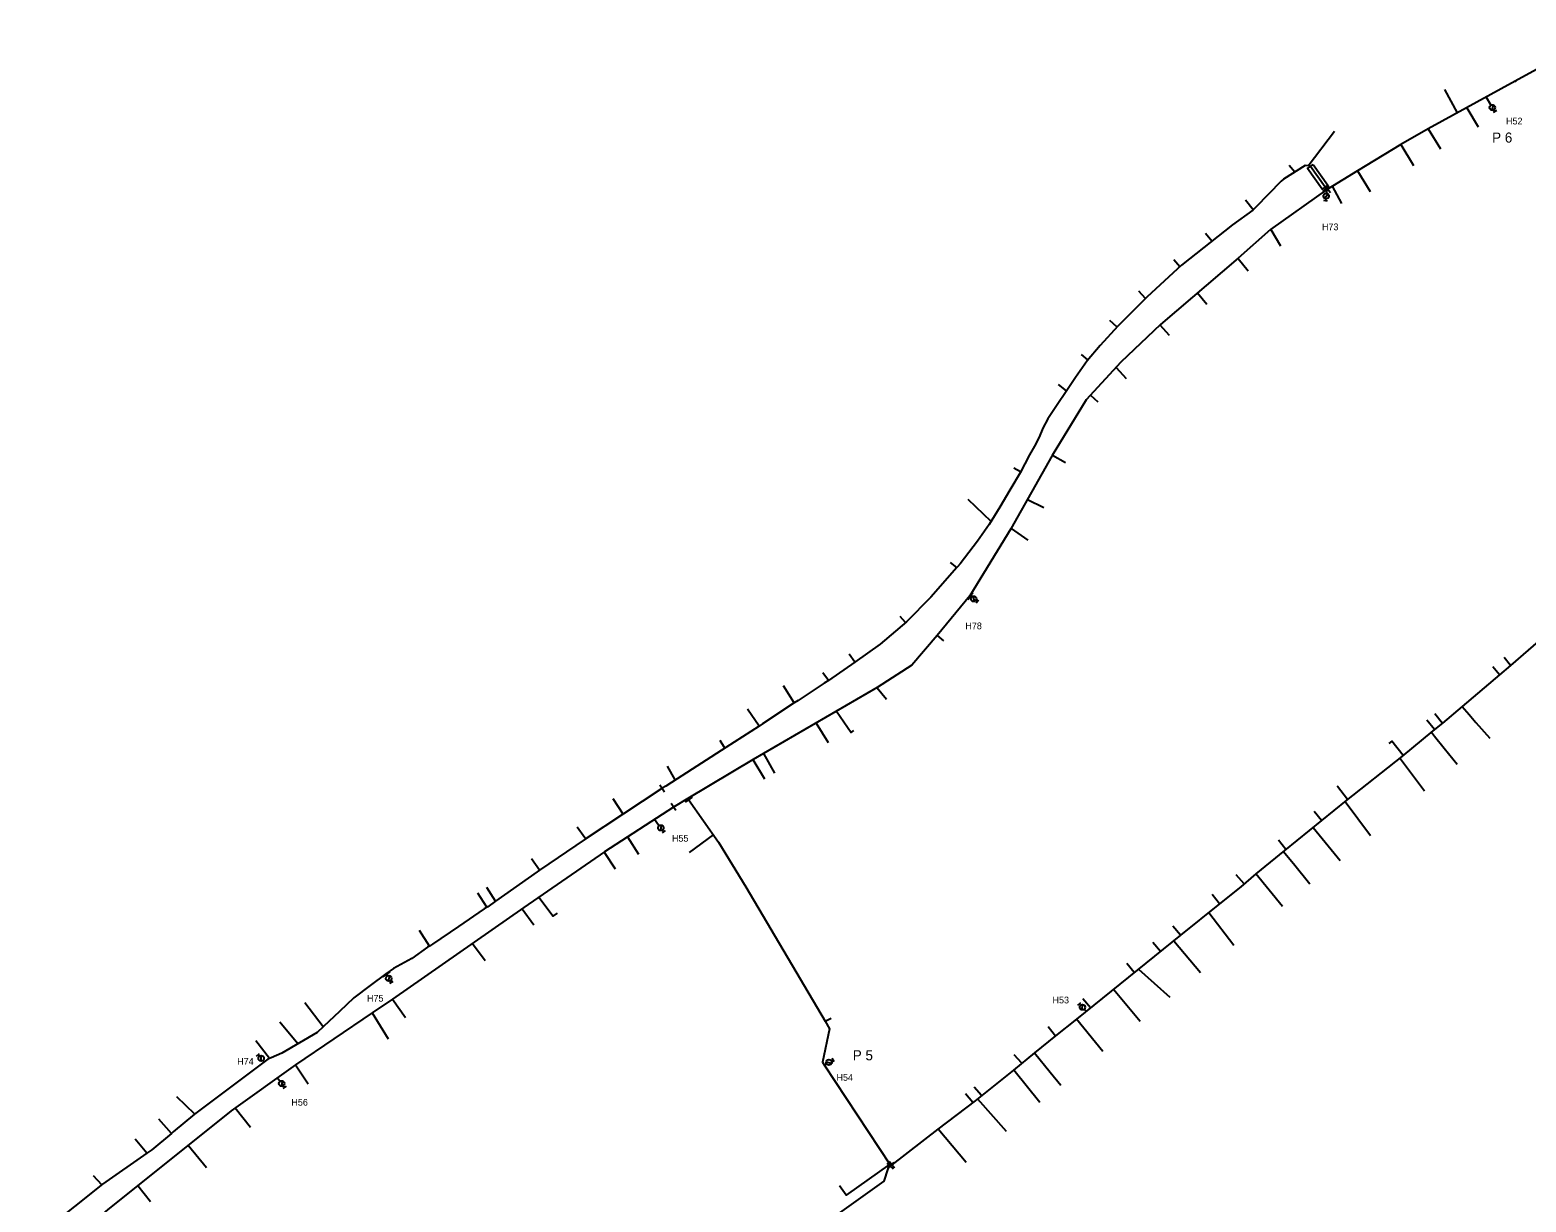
# Model space of a CAD drawing. Extents: x -548873 to -538270, y -1201997 to -1192514.
# Drawn here: x -548075.5 to -547630.3, y -1196272.7 to -1195923.8 of the extents above; entities that cross this region are included whole.
import ezdxf

# ---------------------------------------------------------------- set-up
doc = ezdxf.new("R2010")
doc.units = 0
for name, color, linetype in [('KN_HRAN_STÁTNÍ', 7, 'Continuous'), ('KN_PARC_Č', 7, 'Continuous'), ('KN_VKP_HRAN_SPORNÁ', 7, 'Continuous'), ('PK_PARC_Čv', 7, 'Continuous'), ('Vrstva 29', 7, 'Continuous'), ('Vrstva 37', 7, 'Continuous')]:
    doc.layers.add(name, color=color, linetype=linetype)

# ---------------------------------------------------------------- blocks, each defined once
blk = doc.blocks.new('160')
at = {"layer": 'KN_HRAN_STÁTNÍ'}
blk.add_circle((0, 0), 0.0458, dxfattribs=at)
blk = doc.blocks.new('147')
at = {"layer": 'KN_HRAN_STÁTNÍ'}
blk.add_line((0, 1.27), (0, -1.27), dxfattribs=at)
blk = doc.blocks.new('133')
at = {"layer": 'KN_HRAN_STÁTNÍ'}
for p, q in [((0.28, 0), (0, 0)), ((0.54, 0.58), (1.7, -0.58)), ((1.94, 0), (2.52, 0)), ((2.52, 0.58), (2.52, -0.58))]:
    blk.add_line(p, q, dxfattribs=at)
blk.add_circle((1.11, 0), 0.825, dxfattribs=at)
blk = doc.blocks.new('150')
at = {"layer": 'KN_HRAN_STÁTNÍ'}
blk.add_line((0, 1.27), (0, -1.27), dxfattribs=at)

msp = doc.modelspace()

# ---------------------------------------------------------------- linework, layer by layer
at = {"layer": 'KN_PARC_Č'}
for points in [[(-547650.72, -1195948.422), (-547654.526, -1195941.455)], [(-547647.993, -1195946.932), (-547644.598, -1195952.643)], [(-547659.454, -1195953.193), (-547655.801, -1195959.185)], [(-547695.179, -1195964.212), (-547687.375, -1195953.867)], [(-547667.61, -1195957.858), (-547663.867, -1195964.123)], [(-547699.188, -1195966.12), (-547700.829, -1195964.078)], [(-547680.509, -1195965.705), (-547676.747, -1195971.908)], [(-547688.06, -1195970.3), (-547685.271, -1195975.46)], [(-547676.877, -1195971.694), (-547676.665, -1195971.561)], [(-547711.537, -1195977.275), (-547713.814, -1195974.421)], [(-547723.863, -1195986.662), (-547725.727, -1195984.39)], [(-547706.299, -1195983.155), (-547703.394, -1195988.074)], [(-547733.38, -1195994.29), (-547735.104, -1195992.225)], [(-547716.051, -1195991.783), (-547713.065, -1195995.494)], [(-547743.554, -1196003.691), (-547745.575, -1196001.489)], [(-547728.07, -1196002.028), (-547725.317, -1196005.407)], [(-547752.083, -1196012.197), (-547754.159, -1196010.255)], [(-547739.276, -1196011.598), (-547736.548, -1196014.621)], [(-547760.74, -1196022.007), (-547762.652, -1196020.433)], [(-547752.325, -1196024.284), (-547749.371, -1196027.546)], [(-547767.05, -1196031.215), (-547769.496, -1196029.289)], [(-547759.957, -1196032.504), (-547757.735, -1196034.483)], [(-547771.28, -1196050.367), (-547767.417, -1196052.519)], [(-547780.769, -1196055.293), (-547782.721, -1196054.209)], [(-547789.534, -1196070.153), (-547796.306, -1196063.556)], [(-547778.719, -1196063.571), (-547773.839, -1196065.944)], [(-547783.55, -1196072.151), (-547778.621, -1196075.674)], [(-547799.682, -1196083.771), (-547801.568, -1196082.331)], [(-547814.956, -1196100.182), (-547816.565, -1196098.421)], [(-547805.617, -1196104.09), (-547803.72, -1196105.626)], [(-547830.087, -1196112.005), (-547831.724, -1196109.59)], [(-547638.197, -1196115.765), (-547640.209, -1196113.376)], [(-547634.919, -1196112.931), (-547636.843, -1196110.629)], [(-547837.945, -1196117.408), (-547839.63, -1196115.15)], [(-547848.08, -1196124.063), (-547851.322, -1196119.056)], [(-547823.447, -1196119.602), (-547820.612, -1196123.019)], [(-547858.585, -1196131.012), (-547862.046, -1196125.968)], [(-547835.566, -1196126.62), (-547831.198, -1196132.904), (-547830.328, -1196132.299)], [(-547655.221, -1196130.208), (-547657.496, -1196127.389)], [(-547649.319, -1196125.139), (-547647.281, -1196127.556), (-547645.297, -1196129.91), (-547641.163, -1196134.595)], [(-547841.572, -1196130.098), (-547838.015, -1196135.853)], [(-547657.588, -1196132.075), (-547659.847, -1196129.295)], [(-547868.716, -1196137.581), (-547870.126, -1196135.312)], [(-547666.933, -1196139.727), (-547670.253, -1196135.518), (-547671.144, -1196136.207)], [(-547658.523, -1196132.828), (-547657.575, -1196134.013), (-547654.749, -1196137.548), (-547650.827, -1196142.391)], [(-547857.211, -1196139.154), (-547853.932, -1196145.002)], [(-547667.896, -1196140.502), (-547667.694, -1196140.774), (-547664.99, -1196144.383), (-547660.532, -1196150.246)], [(-547883.506, -1196147.03), (-547885.832, -1196142.922)], [(-547860.41, -1196141.008), (-547856.923, -1196146.75)], [(-547683.456, -1196152.832), (-547686.437, -1196149.039), (-547686.246, -1196148.862)], [(-547899.029, -1196157.195), (-547902.002, -1196152.683)], [(-547901.864, -1196152.892), (-547901.67, -1196152.734)], [(-547684.189, -1196153.419), (-547676.649, -1196163.566)], [(-547691.2, -1196159.119), (-547693.353, -1196156.452)], [(-547910.215, -1196164.623), (-547910.432, -1196164.311), (-547912.681, -1196161.077)], [(-547693.717, -1196161.165), (-547685.68, -1196171.035)], [(-547897.71, -1196164), (-547894.442, -1196169.097)], [(-547872.193, -1196163.358), (-547879.372, -1196168.667)], [(-547701.808, -1196167.741), (-547703.995, -1196165.021)], [(-547923.942, -1196173.943), (-547926.304, -1196170.544)], [(-547904.692, -1196168.542), (-547901.362, -1196173.518)], [(-547702.511, -1196168.31), (-547701.6, -1196169.441), (-547699.566, -1196171.967), (-547694.678, -1196178.005)], [(-547714.25, -1196177.995), (-547716.559, -1196175.302)], [(-547710.729, -1196174.929), (-547702.856, -1196184.652)], [(-547939.531, -1196184.965), (-547942.235, -1196180.745)], [(-547936.966, -1196183.185), (-547939.587, -1196179.059)], [(-547924.144, -1196181.967), (-547919.834, -1196187.647), (-547918.573, -1196186.701)], [(-547721.527, -1196183.919), (-547723.761, -1196181.103)], [(-547929.105, -1196185.396), (-547925.596, -1196190.166)], [(-547724.716, -1196186.486), (-547717.31, -1196196.186)], [(-547956.608, -1196196.484), (-547959.596, -1196191.911)], [(-547733.164, -1196193.287), (-547735.451, -1196190.588)], [(-547943.86, -1196195.697), (-547940.055, -1196200.823)], [(-547739.112, -1196198.076), (-547741.41, -1196195.401)], [(-547735.174, -1196194.905), (-547727.219, -1196204.33)], [(-547746.946, -1196204.383), (-547749.15, -1196201.679)], [(-547745.687, -1196203.37), (-547736.378, -1196211.7)], [(-547753.097, -1196209.335), (-547745.203, -1196218.847)], [(-547988.237, -1196220.539), (-547993.747, -1196213.411)], [(-547973.716, -1196216.412), (-547968.916, -1196224.095)], [(-547967.635, -1196212.296), (-547963.761, -1196217.798)], [(-547759.961, -1196214.861), (-547762.269, -1196212.241)], [(-547995.855, -1196225.64), (-548001.134, -1196219.185)], [(-547838.878, -1196218.83), (-547837.157, -1196217.976)], [(-547770.334, -1196223.277), (-547772.521, -1196220.587)], [(-547764.122, -1196218.212), (-547756.24, -1196227.786)], [(-548004.22, -1196229.965), (-548008.287, -1196224.681)], [(-547780.421, -1196231.398), (-547782.687, -1196228.833)], [(-547776.62, -1196228.252), (-547771.91, -1196234.049), (-547768.747, -1196237.901)], [(-547996.541, -1196231.859), (-547992.75, -1196237.487)], [(-547782.782, -1196233.352), (-547774.999, -1196242.97)], [(-547792.377, -1196241.015), (-547794.556, -1196238.47)], [(-548026.468, -1196246.508), (-548031.791, -1196241.413)], [(-547794.973, -1196243.064), (-547797.134, -1196240.541)], [(-547793.562, -1196241.962), (-547785.035, -1196251.653)], [(-548014.445, -1196244.67), (-548009.938, -1196250.383)], [(-548033.429, -1196252.268), (-548037.135, -1196248.032)], [(-547805.321, -1196250.952), (-547796.91, -1196260.85)], [(-548040.7, -1196258.169), (-548044.196, -1196253.973)], [(-548028.449, -1196255.776), (-548023.031, -1196262.417)], [(-548054.177, -1196267.63), (-548056.607, -1196264.876)], [(-547819.644, -1196261.41), (-547832.69, -1196270.673), (-547834.664, -1196267.922)], [(-548043.447, -1196267.78), (-548039.625, -1196272.532)]]:
    msp.add_lwpolyline(points, dxfattribs=at)
at = {"layer": 'KN_VKP_HRAN_SPORNÁ'}
for points in [[(-547605.577, -1195923.761), (-547633.556, -1195939.045)], [(-547633.556, -1195939.045), (-547659.454, -1195953.193), (-547667.626, -1195957.867), (-547680.512, -1195965.707), (-547689.26, -1195971.03), (-547689.38, -1195971.17)], [(-547689.798, -1195971.058), (-547690.149, -1195970.576), (-547694.51, -1195964.41), (-547694.76, -1195964.25), (-547696.07, -1195964.13), (-547702.48, -1195968.22), (-547703.168, -1195968.828), (-547710.73, -1195976.52), (-547711.65, -1195977.38), (-547717.71, -1195981.77), (-547732.88, -1195993.83), (-547743.107, -1196003.247), (-547751.83, -1196011.92), (-547757.09, -1196017.68), (-547760.97, -1196022.28), (-547764.377, -1196027.201), (-547772.62, -1196039.58), (-547774.08, -1196042.29), (-547775.25, -1196044.99), (-547776.6, -1196047.69), (-547778.13, -1196050.26), (-547780.92, -1196055.58), (-547783.92, -1196060.79), (-547786.94, -1196065.89), (-547790.08, -1196071.05), (-547793.529, -1196075.959), (-547798.692, -1196082.699), (-547799.55, -1196083.62), (-547799.682, -1196083.771), (-547807.434, -1196092.656), (-547814.73, -1196099.99), (-547822.51, -1196106.62), (-547830.08, -1196112), (-547837.945, -1196117.408), (-547839.17, -1196118.25), (-547846.89, -1196123.4), (-547848.17, -1196124.113), (-547857.55, -1196130.34), (-547858.585, -1196131.012), (-547868.48, -1196137.43), (-547882.95, -1196146.67), (-547886.339, -1196148.863), (-547887.43, -1196149.53)], [(-547689.6, -1195971.31), (-547706.342, -1195983.185), (-547716.018, -1195991.755), (-547739.095, -1196011.425), (-547750.876, -1196022.724), (-547761.216, -1196033.861), (-547771.327, -1196050.444), (-547783.633, -1196072.298), (-547795.861, -1196092.263), (-547805.602, -1196104.072), (-547813.151, -1196112.849), (-547823.392, -1196119.57), (-547860.328, -1196140.959), (-547879.783, -1196152.575)], [(-547689.6, -1195971.31), (-547689.798, -1195971.058)], [(-547689.38, -1195971.17), (-547689.6, -1195971.31)], [(-547624.407, -1196103.841), (-547634.919, -1196112.931), (-547638.202, -1196115.77), (-547649.319, -1196125.139), (-547655.2, -1196130.192), (-547658.029, -1196132.423), (-547667.347, -1196140.067), (-547683.871, -1196153.161), (-547702.173, -1196168.038), (-547710.778, -1196174.969), (-547715.223, -1196178.843), (-547721.527, -1196183.919), (-547733.164, -1196193.287), (-547764.129, -1196218.217), (-547770.325, -1196223.27), (-547776.656, -1196228.28), (-547782.855, -1196233.413), (-547794.305, -1196242.555), (-547805.337, -1196250.964), (-547819.06, -1196261.634)], [(-547887.43, -1196149.53), (-547887.84, -1196149.83), (-547898.87, -1196157.09), (-547910.27, -1196164.66), (-547923.942, -1196173.943), (-547924.6, -1196174.39), (-547936.966, -1196183.185), (-547939.32, -1196184.86), (-547940.34, -1196185.37), (-547948.035, -1196190.678), (-547955.72, -1196195.98), (-547956.33, -1196196.333), (-547956.608, -1196196.484), (-547957.25, -1196196.83), (-547961.92, -1196200.24), (-547967.3, -1196203.19), (-547969.66, -1196204.72), (-547974.34, -1196208.22), (-547979.13, -1196211.96), (-547983.45, -1196216), (-547988.174, -1196220.479), (-547990.03, -1196222.24), (-548000.6, -1196228.41), (-548003.74, -1196229.79), (-548004.78, -1196230.17), (-548026.55, -1196246.57), (-548032.919, -1196251.839), (-548033.429, -1196252.268), (-548039.23, -1196257.14), (-548040.699, -1196258.169), (-548053.9, -1196267.41), (-548070.649, -1196280.689)], [(-547879.783, -1196152.575), (-547884.018, -1196155.103)], [(-547879.783, -1196152.575), (-547879.562, -1196152.899)], [(-547879.562, -1196152.899), (-547870.643, -1196165.557), (-547862.554, -1196178.894), (-547838.878, -1196218.83), (-547837.574, -1196221.179), (-547839.721, -1196231.103), (-547839.157, -1196231.896), (-547819.511, -1196261.611)], [(-547884.018, -1196155.103), (-547904.562, -1196168.452), (-547928.525, -1196184.991), (-547967.685, -1196212.331), (-547973.713, -1196216.41), (-547996.541, -1196231.859), (-548015.673, -1196245.549), (-548052.495, -1196275.023), (-548069.353, -1196289.369), (-548075.537, -1196294.421)], [(-547819.554, -1196262.074), (-547820.226, -1196262.796), (-547821.462, -1196266.462), (-547852.317, -1196288.511), (-547859.337, -1196293.86), (-547876.17, -1196305.83), (-547893.897, -1196318.112), (-547901.104, -1196323.04), (-547905.366, -1196325.953), (-547919.606, -1196336.053), (-547927.544, -1196341.477), (-547943.289, -1196353.024), (-547950.215, -1196358.135), (-547962.621, -1196366.813), (-547971.098, -1196372.855), (-548011.638, -1196402.829)], [(-547819.348, -1196261.858), (-547819.366, -1196261.872), (-547819.554, -1196262.074)], [(-547819.511, -1196261.611), (-547819.348, -1196261.858)], [(-547819.06, -1196261.634), (-547819.348, -1196261.858)]]:
    msp.add_lwpolyline(points, dxfattribs=at)
at = {"layer": 'PK_PARC_Čv'}
for points in [[(-547642.213, -1195943.774), (-547640.945, -1195945.918)], [(-547689.6, -1195971.31), (-547689.69, -1195972.135)], [(-547795.861, -1196092.263), (-547795.599, -1196092.465)], [(-547889.664, -1196158.771), (-547888.456, -1196160.433)], [(-547969.66, -1196204.72), (-547969.46, -1196204.93), (-547969.33, -1196205.16)], [(-547761.268, -1196215.914), (-547761.6, -1196215.534)], [(-548005.797, -1196230.936), (-548005.98, -1196230.73)], [(-547839.126, -1196231.943), (-547838.736, -1196231.71)], [(-548001.907, -1196235.699), (-548001.284, -1196236.538)]]:
    msp.add_lwpolyline(points, dxfattribs=at)
at = {"layer": 'Vrstva 37'}
msp.add_lwpolyline([(-547693.694, -1195963.833), (-547689.332, -1195969.998), (-547690.965, -1195971.153), (-547695.326, -1195964.987), (-547693.694, -1195963.833)], dxfattribs=at)

# ---------------------------------------------------------------- block references
at = {"layer": 'PK_PARC_Čv'}
for name, p, xscale, yscale, rotation in [('133', (-547640.945, -1195945.918), 1.0000000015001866, 1.0000000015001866, -59.00000017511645), ('133', (-547689.69, -1195972.135), 1.0011217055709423, 1.0011217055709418, -96.5826098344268), ('150', (-547795.717, -1196092.374), 0.9999999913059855, 0.9999999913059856, -37.00000193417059), ('133', (-547795.599, -1196092.465), 0.9999999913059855, 0.9999999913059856, -37.00000193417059), ('133', (-547888.456, -1196160.433), 0.9999999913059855, 0.9999999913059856, -52.999998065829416), ('150', (-547969.46, -1196204.93), 0.9999999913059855, 0.9999999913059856, -52.999998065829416), ('133', (-547969.33, -1196205.16), 0.9999999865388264, 0.9999999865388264, -59.99999955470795), ('133', (-547761.6, -1196215.534), 1.0000000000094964, 1.0000000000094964, 132.0000013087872), ('133', (-548005.98, -1196230.73), 1.0000000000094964, 1.0000000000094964, 132.0000013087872), ('133', (-547838.736, -1196231.71), 1.0000000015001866, 1.0000000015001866, 30.99999982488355), ('133', (-548001.284, -1196236.538), 0.9999999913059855, 0.9999999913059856, -52.999998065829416)]:
    msp.add_blockref(name, p, dxfattribs=dict(at, xscale=xscale, yscale=yscale, rotation=rotation))
at = {"layer": 'Vrstva 29'}
for name, p, xscale, yscale, rotation in [('160', (-547633.556, -1195939.045), 1.0037042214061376, 1.0037042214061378, 29.379208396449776), ('147', (-547689.798, -1195971.058), 1.000000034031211, 1.0000000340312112, 128.00000040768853), ('147', (-547689.38, -1195971.17), 1.0000000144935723, 1.0000000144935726, 40.99999910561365), ('160', (-547689.6, -1195971.31), 0.9999999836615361, 0.9999999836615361, -98.00000038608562), ('147', (-547887.43, -1196149.53), 0.9999999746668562, 0.999999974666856, 34.00000045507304), ('147', (-547884.018, -1196155.103), 0.9999999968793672, 0.9999999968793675, -147.99999972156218), ('147', (-547879.562, -1196152.899), 1.000000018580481, 1.000000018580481, -54.99999976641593), ('160', (-547879.783, -1196152.575), 1.0045862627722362, 1.0045862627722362, 166.82590928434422), ('147', (-547819.511, -1196261.611), 0.9999999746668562, 0.999999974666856, -55.999999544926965), ('147', (-547819.06, -1196261.634), 1.000000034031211, 1.0000000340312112, -141.99999959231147), ('147', (-547819.554, -1196262.074), 1.0000000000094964, 1.0000000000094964, -132.0000013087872), ('160', (-547819.348, -1196261.858), 1.008377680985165, 1.0083776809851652, 168.37362119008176)]:
    msp.add_blockref(name, p, dxfattribs=dict(at, xscale=xscale, yscale=yscale, rotation=rotation))

# ---------------------------------------------------------------- texts
at = {"layer": 'PK_PARC_Čv'}
for s, height, p in [('H52', 2, (-547636.305, -1195951.908)), ('P 6', 3, (-547640.445, -1195957.308)), ('H73', 2, (-547691.08, -1195983.395)), ('H78', 2, (-547797.179, -1196102.185)), ('H55', 2, (-547884.486, -1196165.423)), ('H75', 2, (-547975.24, -1196213.05)), ('H53', 2, (-547771.25, -1196213.574)), ('P 5', 3, (-547830.696, -1196230.51)), ('H74', 2, (-548013.87, -1196231.83)), ('H54', 2, (-547835.536, -1196236.6)), ('H56', 2, (-547997.734, -1196244.008))]:
    msp.add_text(s, height=height, dxfattribs=at).set_placement(p)

doc.saveas('drawing.dxf')
